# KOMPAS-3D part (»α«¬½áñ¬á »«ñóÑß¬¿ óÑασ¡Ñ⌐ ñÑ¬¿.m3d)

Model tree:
1. Эскиз:1
2. Операция выдавливания:1
     Расстояние 1 = 3
3. Эскиз:2
4. Вырезать элемент выдавливания:1
     Толщина стенки 1 = 2; Расстояние 1 = 10
5. Эскиз:3
6. Вырезать элемент выдавливания:2
     Расстояние 1 = 50
